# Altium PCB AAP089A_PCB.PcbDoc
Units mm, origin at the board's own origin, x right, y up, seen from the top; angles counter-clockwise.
Board outline 65 x 160 mm, 2 copper layers (Top Layer, Bottom Layer), stack 1.575 mm thick; 87 components, 44 nets, 213 pads, 130 vias.
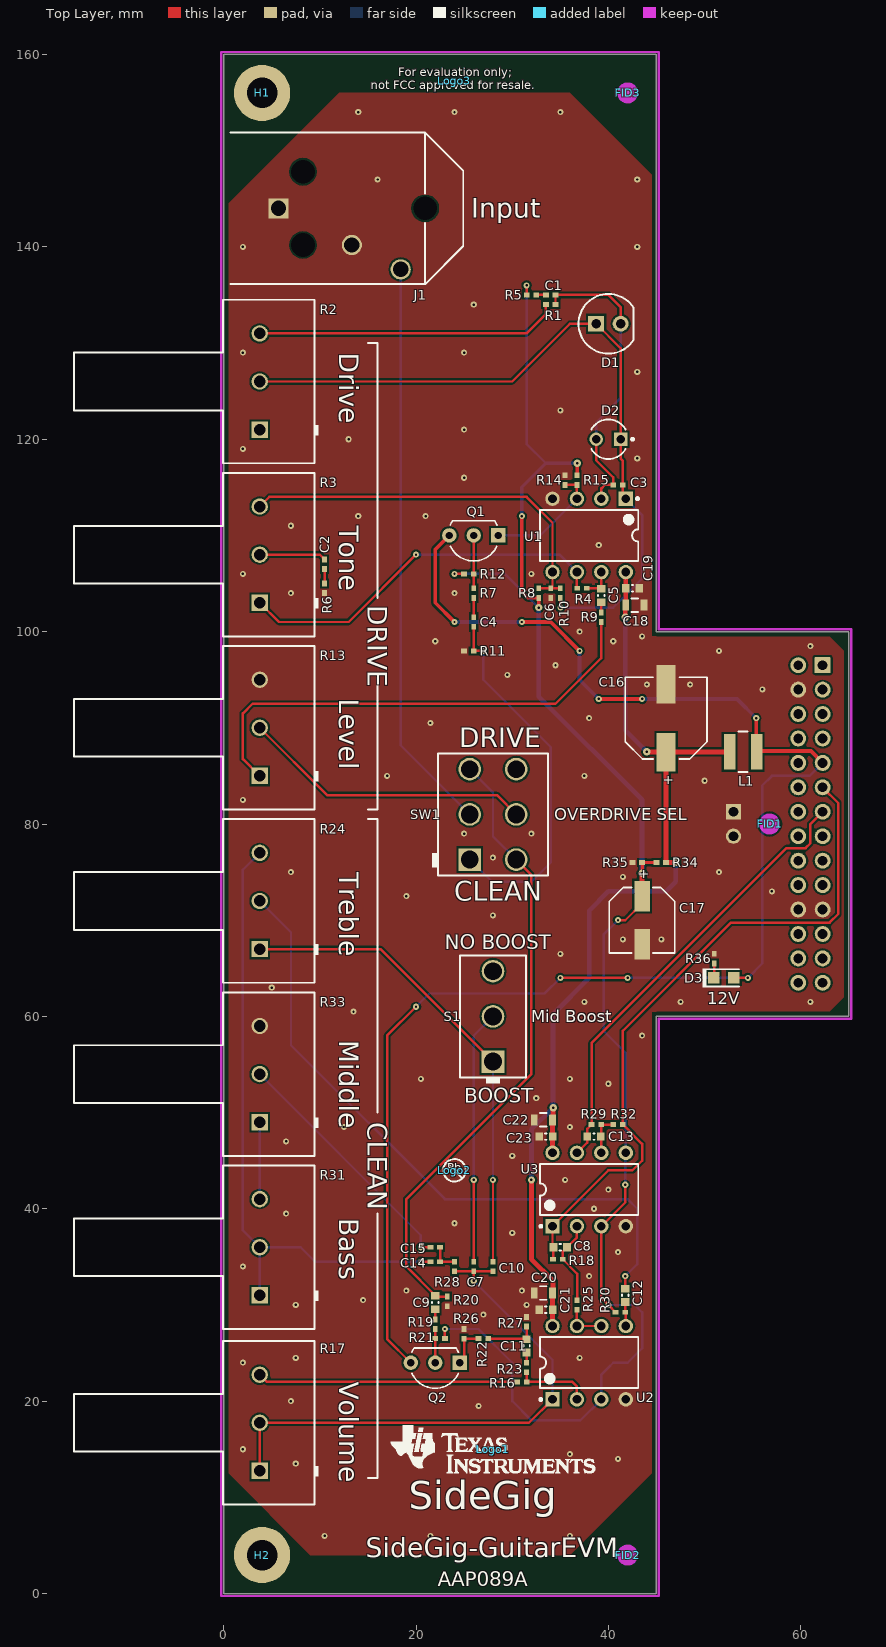
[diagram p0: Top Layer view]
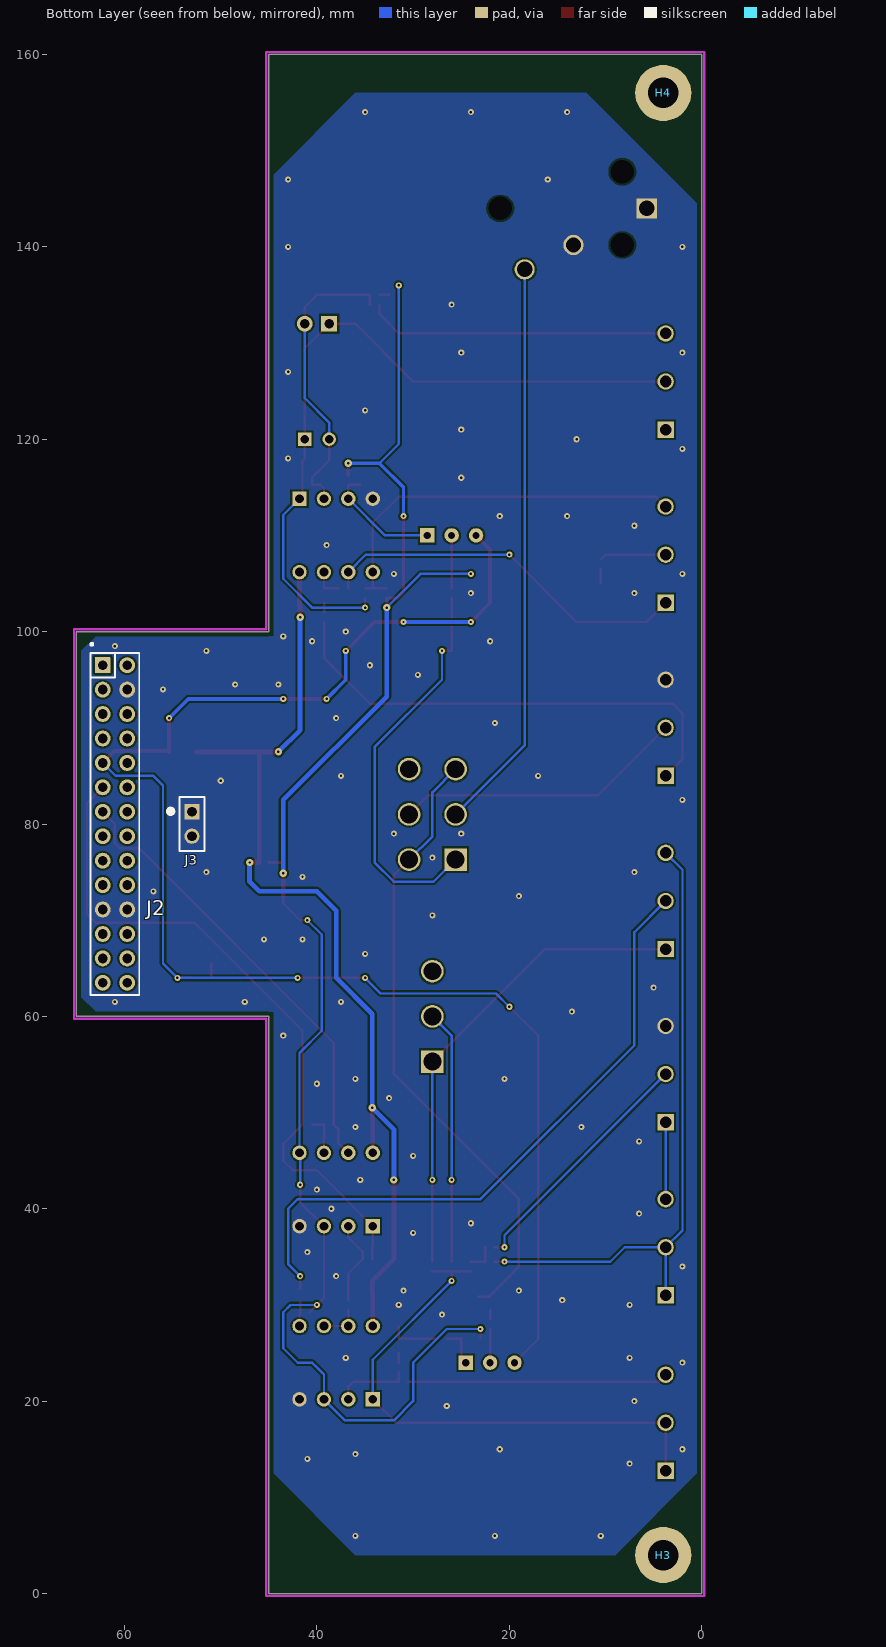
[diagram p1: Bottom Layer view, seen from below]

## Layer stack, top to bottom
Top Solder: solder mask 0.0102, Solder Resist, Dk 3.5
Top Layer: signal copper 0.0356
Dielectric1: core 1.5037, FR-4, Dk 4.8
Bottom Layer: signal copper 0.0356
Bottom Solder: solder mask 0.0102, Solder Resist, Dk 3.5

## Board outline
0,0 45,0 45,60 65,60 65,100 45,100 45,160 0,160

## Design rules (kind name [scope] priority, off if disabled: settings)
AcuteAngle [All] p1: minimum=4.50000000000000E+0001 checktracksonly=FALSE
AssemblyTestPointUsage [All] p1: valid=2
BoardOutlineClearance BoardOutlineClearance_MountingHoles [OnCopper and InComponentClass('Mounting Holes')] p1: gap=0.25
BoardOutlineClearance BoardOutlineClearance_Poly [OnCopper and IsPoly] p2: gap=0.5
BoardOutlineClearance [OnCopper and Not InComponentClass('Logo') and not InComponentClass('FiducialMark') and not InRegion(1000,500,4000,800) and not InPoly] p3: gap=0.5
Clearance Clearance_Keepouts [((IsTrack Or IsArc) And Not InPoly) And IsFree and IsKeepOut vs ((IsTrack Or IsArc) And Not InPoly) And IsFree and IsKeepOut] p1: gap=0
Clearance Clearance_Poly [InPolygon] p2: gap=0.2
Clearance [All] p3: gap=0.2
ComponentClearance ComponentClearance_MountingHoles_FiducialMarks [InComponentClass('Mounting Holes') vs InComponentClass('FiducialMark')] p1: gap=0.25 collisioncheckmode=3 verticalgap=0 showdistances=FALSE
ComponentClearance ComponentClearance_Shunt [InComponentClass('Header') vs InComponentClass('Shunt')] p2: gap=0 collisioncheckmode=3 verticalgap=0 showdistances=FALSE
ComponentClearance ComponentClearance_Logo [InComponentClass('Logo')] p3: gap=1.27 collisioncheckmode=3 verticalgap=0.254 showdistances=FALSE
ComponentClearance ComponentClearance_ScrewToNut [(HasFootprint('NY PMS 440 0025 PH')) vs (HasFootprint('Keystone_1902C'))] p4: gap=0.127 collisioncheckmode=3 verticalgap=0.254 showdistances=FALSE
ComponentClearance ComponentClearance_MountingHoles [InComponentClass('Mounting Holes') vs InComponentClass('Mounting Holes')] p5: gap=0 collisioncheckmode=3 verticalgap=0 showdistances=FALSE
ComponentClearance ComponentClearance_SmallPassives [HasFootprint('0201*') or HasFootprint('0402*') or HasFootprint('0508') or HasFootprint('0603*') or HasFootprint('0612') or HasFootprint('0805*') or HasFootprint('0815*') or HasFootprint('0830*') or HasFootprint('1206*') or HasFootprint('1210*') or HasFootprint('1808*') or HasFootprint('1812*') or HasFootprint('1825*') or HasFootprint('2010*') or HasFootprint('2220*') or HasFootprint('2225*') or HasFootprint('2512*') or HasFootprint('2728*') or HasFootprint('3518*') vs HasFootprint('0201*') or HasFootprint('0402*') or HasFootprint('0508') or HasFootprint('0603*') or HasFootprint('0612') or HasFootprint('0805*') or HasFootprint('0815*') or HasFootprint('0830*') or HasFootprint('1206*') or HasFootprint('1210*') or HasFootprint('1808*') or HasFootprint('1812*') or HasFootprint('1825*') or HasFootprint('2010*') or HasFootprint('2220*') or HasFootprint('2225*') or HasFootprint('2512*') or HasFootprint('2728*') or HasFootprint('3518*')] p6: gap=0.38 collisioncheckmode=3 verticalgap=0.254 showdistances=FALSE
ComponentClearance ComponentClearance_THtoSMT [IsThruComponent vs IsSMTComponent] p7: gap=1.016 collisioncheckmode=3 verticalgap=0.762 showdistances=FALSE
ComponentClearance ComponentClearance_THtoTH [IsThruComponent vs IsThruComponent] p8: gap=0.762 collisioncheckmode=3 verticalgap=0.762 showdistances=FALSE
ComponentClearance [All] p9: gap=0.762 collisioncheckmode=3 verticalgap=0.254 showdistances=FALSE
DiffPairsRouting [All] p1: maxlimit=2.54 minlimit=0.254 mostfreqgap=0.254 toplayer_minwidth=0.381 toplayer_maxwidth=0.381 toplayer_prefwidth=0.381 bottomlayer_minwidth=0.381 bottomlayer_maxwidth=0.381 bottomlayer_prefwidth=0.381 maxuncoupledlength=25.4
FabricationTestPointUsage TestPointUsage [All] p1: valid=2 allowmultiple=FALSE
FabricationTestpoint Testpoint [All] p1: side=3 testpointundercomponent=TRUE minsize=1.016 maxsize=2.54 preferedsize=1.524 minholesize=0 maxholesize=1.016 preferedholesize=0.813 testpointgrid=0.025 allowsidetop=TRUE allowsidebottom=TRUE usegrid=TRUE gridtolerance=0
FanoutControl Fanout_LCC [IsLCC] p1: bgadir=Out bgaviamode=Centered fanoutstyle=Auto fanoutdirection=Alternating viagrid=0.025 // Fanout_LCC (Default Rule)
FanoutControl Fanout_BGA [IsBGA] p2: bgadir=Out bgaviamode=Centered fanoutstyle=Auto fanoutdirection=Alternating viagrid=0.025 // Fanout_BGA (Default Rule)
FanoutControl Fanout_Default [All] p4: bgadir=Out bgaviamode=Centered fanoutstyle=Auto fanoutdirection=Alternating viagrid=0.025 // Fanout_Default (Default Rule)
FanoutControl Fanout_Small [(CompPinCount < 5)] p5: bgadir=Out bgaviamode=Centered fanoutstyle=Auto fanoutdirection=OutThenIn viagrid=0.025 // Fanout_Small (Default Rule)
Height [All] p1: minheight=0 maxheight=38.1 prefheight=12.7
HoleSize [All] p1: absolutevalues=TRUE maxlimit=6.375 minlimit=0.2 maxpercent=80.000 minpercent=20.000
MinimumAnnularRing MinimumAnnularRing_ThermalPadVias [IsVia and InAnyComponent] p1: minimumring=0.15
MinimumAnnularRing [All] p2: minimumring=0.127
MinimumSolderMaskSliver MinimumSolderMaskSliver_Logo [InComponentClass('Logo') vs InComponentClass('Logo')] p1: minsoldermaskwidth=0.018
MinimumSolderMaskSliver [All] p2: minsoldermaskwidth=0.1
PlaneConnect [All] p1: planeconnectstyle=Relief reliefexpansion=0.254 reliefentries=4 reliefconductorwidth=0.254 reliefairgap=0.254
PolygonConnect PreFlood [All] p1: connectstyle=Direct reliefconductorwidth=0.254 reliefentries=4 polygonreliefangle="90 Angle" airgapwidth=0.254
RoutingVias ThermalPadVias [IsVia and InAnyComponent] p1: holewidth=0.2 width=0.5 viastyle="Through Hole" minholewidth=0.2 minwidth=0.5 maxholewidth=0.33 maxwidth=0.6
RoutingVias [All] p2: holewidth=0.254 width=0.635 viastyle="Through Hole" minholewidth=0.254 minwidth=0.635 maxholewidth=1.016 maxwidth=1.651
SilkToBoardRegionClearance [Not ((IsComment or IsDesignator) And (Hide <> 'False')) and not InRegion(1000,500,4000,800)] p1:
SilkToSilkClearance SilkToSilkClearance_Pb-FreeLogo [(HasFootprint('Pb-Free_Overlay_Medium') OR HasFootprint('Pb-Free_Overlay_Small')) vs (HasFootprint('Pb-Free_Overlay_Medium') OR HasFootprint('Pb-Free_Overlay_Small'))] p1: silktosilkclearance=0
SilkToSilkClearance [All] p2: silktosilkclearance=0.102
SilkToSolderMaskClearance SilkToComponentPadClearance [IsPad and InAnycomponent] p1: minsilkscreentomaskgap=0.127 clearancetoexposedcopper=TRUE
SilkToSolderMaskClearance "Silk to Solder Mask Opening" [All] p2: minsilkscreentomaskgap=0.102 clearancetoexposedcopper=FALSE
SolderMaskExpansion [All] p1: expansion=0.05
Width [All] p1: maxlimit=2.54 minlimit=0.152 preferedwidth=0.254 checkconnectedcopper=TRUE
14 further rules are at their usual default settings.

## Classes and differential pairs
component class "Mounting Holes": H1 H2 H3 H4
component class Header: J2
component class AAP089A_SideGig-GuitarEVM: C1 C2 C3 C4 C5 C6 C7 C8 C9 C10 C11 C12 C13 C14 C15 C16 C17 C18 C19 C20 C21 C22 C23 D1 D2 D3 J1 J2 J3 L1 Q1 Q2 R1 R2 R3 R4 R5 R6 R7 R8 R9 R10 R11 R12 R13 R14 R15 R16 R17 R18 R19 R20 R21 R22 R23 R24 R25 R26 R27 R28 R29 R30 R31 R32 R33 R34 R35 R36 S1 SW1 U1 U2 U3
component class Logo: Logo1
component class AAP089A_EVM_Hardware: FID1 FID2 FID3 H1 H2 H3 H4 Logo1 Logo2 Logo3 ZZ1 ZZ2 ZZ3 ZZ4
component class FiducialMark: FID1 FID2 FID3
component class AssemblyNote: ZZ1 ZZ2 ZZ3 ZZ4

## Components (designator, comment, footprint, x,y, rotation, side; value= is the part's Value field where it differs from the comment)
C1 "GRM155R71E473KA88D" 0402L 34,135 r0 top
C2 "GRM155R71C224KA12D" 0402L 10.5,107 r90 top
C3 "GRM1555C1H510JA01D" 0402L 41,115.25 r0 top
C4 "GRM155R71E473KA88D" 0402L 26,101 r90 top
C5 "UMK107AB7105KA-T" 0603L 39.25,103.75 r270 top
C6 "GRM155R71C224KA12D" 0402L 34,104 r90 top
C7 "GRM1555C1H471JA01D" 0402L 26,34 r90 top
C8 "GRM1885C1H220JA01D" 0603L 35,36 r0 top
C9 "C0603C104K5RACTU" 0603L 22,30.25 r270 top
C10 "GRM1555C1H471JA01D" 0402L 28,34 r90 top
C11 "GRM188R61A106ME69D" 0603L 31.5,25.75 r270 top
C12 "GRM188R61A106ME69D" 0603L 41.75,31 r270 top
C13 "GRM1885C1H220JA01D" 0603L 38.5,47.5 r0 top
C14 "GRM155R71H222KA01D" 0402L 22,34.5 r180 top
C15 "GRM155R71H222KA01D" 0402L 22,36 r180 top
C16 "+" SM_RADIAL_F 46,91 r90 top
C17 "+" SM_RADIAL_D 43.5,70 r270 top
C18 "EMK212BJ106KG-T" 0805_KTR 42.75,102.75 r0 top
C19 "C0603C104K5RACTU" 0603L 42.5,104.5 r0 top
C20 "EMK212BJ106KG-T" 0805_KTR 33.25,31.25 r180 top
C21 "C0603C104K5RACTU" 0603L 33.5,29.5 r180 top
C22 "EMK212BJ106KG-T" 0805_KTR 33.25,49.25 r180 top
C23 "C0603C104K5RACTU" 0603L 33.5,47.5 r180 top
D1 "HLMP-3316" HLMP-331_RED 40,132 r0 top
D2 "LTL1CHTBK4" LTL1CH_Blue 40,120 r180 top
D3 "12V" LED_LTST-C171 52,64 r180 top
FID1 "Fiducial" Fiducial10-20 56.75,80 r0 top
FID2 "Fiducial" Fiducial10-20 42,4 r0 top
FID3 "Fiducial" Fiducial10-20 42,156 r0 top
H1 "4-40x1/4\"" B_F_PMSSS4400025PH 4,156 r0 top
H2 "4-40x1/4\"" B_F_PMSSS4400025PH 4,4 r0 top
H3 "4-40x1-1/2\"" Keystone_3483 4,4 r180 bottom
H4 "4-40x1-1/2\"" Keystone_3483 4,156 r180 bottom
J1 "Input" Switchcraft_RN112APC 8.25,144 r180 top
J2 "" TSW-114-07-G-D 61,80 r270 bottom
J3 "PPTC021LFBN-RC" CONN_PPTC021LFBN-RC 53,80 r90 bottom locked
L1 "NRS4012T100MDGJV" NRS4012 54,87.5 r180 top
Logo1 "Texas Instruments" TI_Stacked_Overlay_Small 28,15 r0 top
Logo2 "Pb-Free Symbol" Pb-Free_Overlay_Small 24,44 r0 top
Logo3 "FCC disclaimer" FCC_disclaimer_stacked 24,157.25 r0 top
Q1 "2N4401" TO-92AP 26,110 r180 top
Q2 "2N4401" TO-92AP 22,24 r180 top
R1 "ERJ-2RKF5102X" 0402L 34,134 r180 top
R2 "Drive" BITechnology_P160KN-0QC15 3.75,126 r90 top
R3 "Tone" BITechnology_P160KN-0QC15 3.75,108 r90 top
R4 "CRCW04021K00FKED" 0402L 37.25,104.5 r180 top
R5 "ERJ-2RKF4701X" 0402L 32,135 r180 top
R6 "ERJ-2RKF2200X" 0402L 10.5,104.5 r270 top
R7 "CRCW04021K00FKED" 0402L 26,104 r270 top
R8 "ERJ-2RKF1002X" 0402L 32.75,104 r90 top
R9 "CRCW04021K00FKED" 0402L 39.25,101.5 r90 top
R10 "CRCW04021K00FKED" 0402L 35,104 r270 top
R11 "CRCW04021M50FKED" 0402L 25.5,98 r0 top
R12 "RC0402FR-07470KL" 0402L 25.5,106 r0 top
R13 "Level" BITechnology_P160KN-0QC15 3.75,90 r90 top
R14 "ERJ-2RKF1002X" 0402L 35.5,115.75 r90 top
R15 "ERJ-2RKF1002X" 0402L 36.75,115.75 r90 top
R16 "CRCW04022K74FKED" 0402L 31,22 r0 top
R17 "Volume" BITechnology_P160KN-0QC15 3.75,17.75 r90 top
R18 "ERJ-2RKF1002X" 0402L 34.75,34.75 r180 top
R19 "CRCW04021K00FKED" 0402L 22,28 r90 top
R20 "CRCW04021M50FKED" 0402L 23.25,30.375 r90 top
R21 "RC0402FR-07470KL" 0402L 22.5,26.5 r180 top
R22 "CRCW0402100RFKED" 0402L 27,26.5 r0 top
R23 "CRCW04021K00FKED" 0402L 31.5,23.5 r90 top
R24 "Treble" BITechnology_P160KN-0QC15 3.75,72 r90 top
R25 "ERJ-2RKF1002X" 0402L 36.75,30 r90 top
R26 "ERJ-2RKF1002X" 0402L 25,27 r90 top
R27 "RC0402FR-07470KL" 0402L 31.5,28.25 r270 top
R28 "CRCW040233K2FKED" 0402L 24,34 r90 top
R29 "ERJ-2RKF1002X" 0402L 38.75,48.75 r180 top
R30 "RC0402FR-07470KL" 0402L 41.25,29.25 r0 top
R31 "Bass" BITechnology_P160KN-0QC15 3.75,36 r90 top
R32 "ERJ-2RKF1002X" 0402L 41,48.75 r180 top
R33 "Middle" BITechnology_P160KN-0QC15 3.75,54 r90 top
R34 "ERJ-2RKF1002X" 0402L 45.5,76 r180 top
R35 "ERJ-2RKF1002X" 0402L 43,76 r180 top
R36 "CRCW04021K50FKED" 0402L 51,66 r90 top
S1 "Mid Boost" SW_100SP1T1B1M2QEH 28,60 r90 top
SW1 "OVERDRIVE SEL" SW_100DP1T1B1M2QEH 28,81 r90 top
U1 "RC4558IP" P0008A 38,110 r270 top
U2 "NE5532AP" P0008A 38,24 r90 top
U3 "NE5532AP" P0008A 38,42 r90 top
ZZ1 "U1, U2 and U3 are to be inserted into XU1, XU2, and XU3. Only the dip sockets are to soldered directly to the board." AssemblyNote 4,170 r0 top
ZZ2 "These assemblies are ESD sensitive, ESD precautions shall be observed." AssemblyNote 4,166 r0 top
ZZ3 "These assemblies must be clean and free from flux and all contaminants. Use of no clean flux is not acceptable." AssemblyNote 4,164 r0 top
ZZ4 "These assemblies must comply with workmanship standards IPC-A-610 Class 2, unless otherwise specified." AssemblyNote 4,168 r0 top

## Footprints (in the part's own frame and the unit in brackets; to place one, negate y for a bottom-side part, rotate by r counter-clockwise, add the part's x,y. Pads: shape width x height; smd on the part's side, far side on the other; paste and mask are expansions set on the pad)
0402L [mm] "0402 from SM-752 data"
  rect 0.6x0.5 smd: 1(-0.5,0) 2(0.5,0)
  body extent -0.55,-0.3 0.55,0.3, height 0.6
0603L [mm] "0603 from SM-752 data"
  rect 0.8x0.85 smd: 1(-0.7,0) 2(0.7,0)
  silkscreen extent -0.07,-0.33 0.07,0.33, body extent -0.87,-0.47 0.87,0.47, height 1
0805_KTR [mm] "ROHM"
  rect 0.7x1.15 smd: 1(-0.95,0) 2(0.95,0)
  silkscreen extent -0.35,-0.7 0.35,0.7, body extent -1.05,-0.67 1.05,0.67, height 0.65
AssemblyNote [mm] "Assembly Note"
B_F_PMSSS4400025PH [mil] "MACHINE SCREW PAN PHILLIPS 4-40"
  round 230 hole 125: 1(0,0)
  body extent -109,-109 110,110, height 79
BITechnology_P160KN-0QC15 [mm] "TH, 3-Leads, Body 17x24.5mm"
  rect 1.7x1.7 hole 1.2: 1(-5,0)
  round 1.7 hole 1.2: 2(0,0) 3(5,0)
  silkscreen extent -8.5,-6.1 8.5,19.3, body extent -8.5,-5.7 8.5,19.3, height 21
CONN_PPTC021LFBN-RC [mil] "SULLINS"
  rect 62x62 hole 40: 1(50,0)
  round 62 hole 40.16: 2(-50,0)
  silkscreen extent -111,-51 111,97, body extent -110,-50 110,50, height 336
FCC_disclaimer_stacked [mm]
Fiducial10-20 [mm]
  round 1 smd mask+0.5: 1(0,0)
  Top Layer keep-out circle w1.178: c0,0 r0.5
HLMP-331_RED [mm] "AVAGO"
  rect 1.65x1.65 hole 1: 1(-1.27,0)
  round 1.65 hole 1: 2(1.27,0)
  silkscreen extent -3.1,-3.1 2.6,3.1, body extent -3.05,-3.06 2.57,3.06, height 11.19
Keystone_3483 [mm] "1/4 Round Female Standoff"
  body extent -3.17,-3.17 3.18,3.18, height 38.1
LED_LTST-C171 [mm] "LITE-ON"
  rect 1.2x1.2 smd: 1(-1.05,0) 2(1.05,0)
  silkscreen extent -1.6,-1 2.2,1, body extent -1.05,-0.67 1.05,0.67, height 0.8
LTL1CH_Blue [mm] "TH, 2-Leads, Dia 3.8mm, Pin Spacing 2.54mm"
  rect 1.4x1.4 hole 0.9: 1(-1.27,0)
  round 1.4 hole 0.9: 2(1.27,0)
  silkscreen extent -2.65,-2.05 1.78,2.05, body extent -2.05,-2.05 2.05,2.05, height 6.5
NRS4012 [mm] "2-Leads SMD, Body 4.2x4.2mm, Height 1.2mm"
  rect 1.2x3.7 smd: 1(-1.4,0) 2(1.4,0)
  silkscreen extent -0.49,-2.1 0.49,2.1, body extent -2.1,-2.1 2.1,2.1, height 1.2
P0008A [mm] "DIP, 8-Leads, Row Spacing 7.62mm, Pitch 2.54mm, Body 9.6x6.4mm"
  rect 1.5x1.5 hole 0.9: 1(-3.81,3.81)
  round 1.5 hole 0.9: 2(-3.81,1.27) 3(-3.81,-1.27) 4(-3.81,-3.81) 5(3.81,-3.81) 6(3.81,-1.27) 7(3.81,1.27) 8(3.81,3.81)
  silkscreen extent -3.95,-5.1 2.65,5.15, body extent -4.1,-4.64 4.1,4.64, height 4.22
Pb-Free_Overlay_Small [mm]
  silkscreen extent -1.16,-1.17 1.17,1.17
SM_RADIAL_D [mm] "6.3 x 5.8mm:  Panasonic D"
  rect 3.2x1.6 smd: 1(-2.5,0) 2(2.5,0)
  silkscreen extent -3.4,-3.4 3.4,3.4, body extent -3.4,-3.4 3.4,3.4, height 6.1
SM_RADIAL_F [mm] "8 x 10.2mm:  Panasonic F"
  rect 4x2 smd: 1(-3.55,0) 2(3.55,0)
  silkscreen extent -4.25,-4.25 4.25,4.25, body extent -4.25,-4.25 4.25,4.25, height 10.5
SW_100DP1T1B1M2QEH [mm] "TH, 6-Leads, Body 12.7x11.43mm, Pitch 4.7mm"
  rect 2.35x2.35 hole 1.85: 1(-4.7,2.415)
  round 2.35 hole 1.85: 2(0,2.415) 3(4.7,2.415) 4(-4.7,-2.415) 5(0,-2.415) 6(4.7,-2.415)
  silkscreen extent -6.35,-5.71 6.35,6.36, body extent -6.35,-5.71 6.35,5.72, height 29.99
SW_100SP1T1B1M2QEH [mm] "TH, 3-Leads, Body 12.7x6.86mm, Pitch 4.7mm"
  rect 2.35x2.35 hole 1.85: 1(-4.7,0)
  round 2.35 hole 1.85: 2(0,0) 3(4.7,0)
  silkscreen extent -7,-3.43 6.35,3.43, body extent -6.35,-3.43 6.35,3.43, height 28.49
Switchcraft_RN112APC [mm] "Audio Jack, 3-Pos, R/A, TH"
  rect 2.1x2.1 hole 1.6: 1(2.54,0)
  round 2.1 hole 1.6: 2(-10.16,6.35) 3(-5.08,3.81)
  round 1.524 hole 2.45 unplated: MH1(-12.7,0) MH2(0,3.81) MH3(0,-3.81)
  silkscreen extent -16.66,-7.87 7.54,7.87, body extent -16.66,-7.87 15.85,7.87, height 17.27
TI_Stacked_Overlay_Small [mm]
  silkscreen extent -10.63,-2.49 10.63,2.49
TO-92AP [mm] "TO, Flat Index; 3 In-Line, Axial Leads; Body Dia. 5mm; Leads 0.55 x 0.50 mm (max)"
  rect 1.5x1.5 hole 0.75: 1(-2.54,0)
  round 1.5 hole 0.75: 2(0,0) 3(2.54,0)
  silkscreen extent -2.42,-1.53 2.44,2.66, body extent -2.87,-1.53 2.87,2.66, height 9.33
TSW-114-07-G-D [mm] "Samtec 100mil, 2x14, 230 mil above insulator"
  rrect6% 1.65x1.65 hole 1.016: 1(-16.51,-1.27)
  round 1.65 hole 1.016: 2(-16.51,1.27) 3(-13.97,-1.27) 4(-13.97,1.27) 5(-11.43,-1.27) 6(-11.43,1.27) 7(-8.89,-1.27) 8(-8.89,1.27) 9(-6.35,-1.27) 10(-6.35,1.27) 11(-3.81,-1.27) 12(-3.81,1.27) 13(-1.27,-1.27) 14(-1.27,1.27) 15(1.27,-1.27) 16(1.27,1.27) 17(3.81,-1.27) 18(3.81,1.27) 19(6.35,-1.27) 20(6.35,1.27) 21(8.89,-1.27) 22(8.89,1.27) 23(11.43,-1.27) 24(11.43,1.27) 25(13.97,-1.27) 26(13.97,1.27) 27(16.51,-1.27) 28(16.51,1.27)
  silkscreen extent -18.8,-2.54 17.78,2.54, body extent -17.78,-2.54 17.78,2.54, height 8.38

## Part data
C1 C4: "CAP, CERM, 0.047 µF, 25 V, +/- 10%, X7R, 0402"
C2 C6: "CAP, CERM, 0.22 µF, 16 V, +/- 10%, X7R, 0402"
C3: "CAP, CERM, 51 pF, 50 V, +/- 5%, C0G/NP0, 0402"
C5: "CAP, CERM, 1 µF, 50 V, +/- 10%, X7R, 0603"
C7 C10: "CAP, CERM, 470 pF, 50 V, +/- 5%, C0G/NP0, 0402"
C8 C13: "CAP, CERM, 22 pF, 50 V, +/- 5%, C0G/NP0, 0603"
C9 C19 C21 C23: "CAP, CERM, 0.1 µF, 50 V, +/- 10%, X7R, 0603"
C11 C12: "CAP, CERM, 10 µF, 10 V, +/- 20%, X5R, 0603"
C14 C15: "CAP, CERM, 2200 pF, 50 V, +/- 10%, X7R, 0402"
C16: library part EEE-FC1E101P, "CAP, AL, 100 µF, 25 V, +/- 20%, 0.3 ohm, SMD"
C17: library part EEE-FK1C470P, "CAP, AL, 47 µF, 16 V, +/- 20%, 0.36 ohm, SMD"
C18 C20 C22: "CAP, CERM, 10 µF, 16 V, +/- 10%, X5R, 0805"
D1: "LED, Red, TH"
D2: "LED, Blue, TH"
D3: library part LTST-C171GKT, "LED, Green, SMD"
FID1 FID2 FID3: "Fiducial mark.  There is nothing to buy or mount."
H1 H2: library part "PMSSS 440 0025 PH", "MACHINE SCREW PAN PHILLIPS 4-40"
H3 H4: library part 3483, "1/4 Round Female Standoff, Alum, 1-1/2\""
J1: library part RN112APC, "Audio Jack, 1/4\", Headphone Phone Jack Mono, R/A, Black, TH"
J2: library part TSW-114-07-G-D, "Header, 100mil, 14x2, Gold, TH"
J3: "Receptacle, 100mil, 2x1, Tin, TH"
L1: "Inductor, Wirewound, 10 µH, 0.8 A, 0.204 ohm, SMD"
Logo1: library part TI_Logo, "Texas Instrument Corporate Signature"
Logo2: library part Pb-Free
Logo3: library part FCC_disclaimer, "FCC_disclaimer"
Q1 Q2: library part "2N4401-AP, Micro Commercial Components", "Transistor, NPN, 40 V, 0.5 A, TO-92AP"
R1: "RES, 51.0 k, 1%, 0.1 W, AEC-Q200 Grade 0, 0402"
R2: library part P160KN-0QC15A500K, "Potentiometer 500K 20% 16MM ROTARY POT, TH"
R3 R17 R33: library part P160KN-0QC15B20K, "Potentiometer 20K 20% 16MM ROTARY POT, TH"
R4 R7 R9 R10 R19 R23: "RES, 1.00 k, 1%, 0.063 W, 0402"
R5: "RES, 4.70 k, 1%, 0.1 W, 0402"
R6: "RES, 220, 1%, 0.1 W, AEC-Q200 Grade 0, 0402"
R8 R14 R15 R18 R25 R26 R29 R32 R34 R35: "RES, 10.0 k, 1%, 0.1 W, 0402"
R11 R20: "RES, 1.50 M, 1%, 0.063 W, 0402"
R12 R21 R27 R30: "RES, 470 k, 1%, 0.0625 W, 0402"
R13: library part P160KN-0QC15A100K, "Potentiometer 100K 20% 16MM ROTARY POT, TH"
R16: "RES, 2.74 k, 1%, 0.063 W, 0402"
R22: "RES, 100, 1%, 0.063 W, 0402"
R24: library part P160KN-0QC15B250K, "Potentiometer 250K 20% 16MM ROTARY POT, TH"
R28: "RES, 33.2 k, 1%, 0.063 W, 0402"
R31: library part P160KN-0QC15A1MEG, "Potentiometer 1Meg 20% 16MM ROTARY POT, TH"
R36: "RES, 1.50 k, 1%, 0.063 W, 0402"
S1: library part 100SP1T1B1M2QEH, "Switch, SPDT, On-On, 5 A, 120 VAC, 28 VDC, TH"
SW1: library part 100DP1T1B1M2QEH, "Switch, DPDT, On-On, 5 A, 120 VAC, 28 VDC, TH"
U1: "Dual General-Purpose Operational Amplifier, 10 to 30 V, -40 to 85 degC, 8-pin DIP (P0008A), Pb-Free (RoHS)"
U2 U3: "Dual Low-Noise Operational Amplifier, 10 to 30 V, 0 to 70 degC, 8-pin DIP (P0008A), Pb-Free (RoHS)"
ZZ1 ZZ2 ZZ3 ZZ4: library part AssemblyNote

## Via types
v1: diameter 0.635, hole 0.254, Top Layer to Bottom Layer, tented both sides, 122 vias
v2: diameter 0.762, hole 0.254, Top Layer to Bottom Layer, tented both sides, 8 vias

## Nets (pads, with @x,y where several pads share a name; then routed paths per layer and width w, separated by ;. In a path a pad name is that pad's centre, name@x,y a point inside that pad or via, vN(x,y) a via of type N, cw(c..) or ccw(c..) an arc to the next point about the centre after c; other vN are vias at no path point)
+12V: D3.1 J2.9 L1.1 Q1.3 Q2.3 | length 163
  Top Layer w0.25: Q2.3 17,26.46 17,58 v1(20,61) ; v1(35,64) v1(42,64) ; D3.1 v1(54.5,64)
  Top Layer w0.4: Q1.3 22,108.54 22,103 v1(24,101) ; v1(31,101) 34,101 v1(37,98) ; v1(39,93) v1(43.5,93) ; L1.1@55.375,87.5 55.45,87.575 61.045,87.575 J2.9 ; v1(55.375,91) 55.375,87.525 55.388,87.513 L1.1
  Bottom Layer w0.25: v1(20,61) 21.375,62.375 33.375,62.375 v1(35,64) ; v1(42,64) v1(54.5,64) 56,65.5 56,84 57,85 60.92,85 J2.9
  Bottom Layer w0.4: v1(24,101) v1(31,101) ; v1(37,98) 37,95 v1(39,93) ; v1(43.5,93) 53.375,93 v1(55.375,91)
+12V-OA: C16.1 C18.1 C19.1 C20.1 C21.1 C22.1 C23.1 L1.2 R34.1 U1.8 U2.8 U3.8 | length 104.3
  Top Layer w0.254: C23.1@34.19,47.49 C23.1 ; C22.1 C22.1@34.25,49.3
  Top Layer w0.5: v2(32,43) 32,34.75 34.25,32.5 34.25,31.3 C20.1 C21.1 34.19,29.49 U2.8 ; U3.8 C23.1@34.19,47.49 ; C23.1 C22.1 ; C22.1@34.25,49.3 v2(34.25,50.5) ; v2(41.75,101.5) 41.75,102.7 C18.1 C19.1 41.81,104.51 U1.8 ; v2(44,87.5) L1.2 ; C16.1 R34.1 v2(47,76)
  Bottom Layer w0.5: v2(32,43) 32,48.25 v2(34.25,50.5) 34.25,60.25 38,64 38,71 40,73 46,73 47,74 v2(47,76) ; v2(41.75,101.5) 41.75,89.75 v2(44,87.5)
GND: C6.1 C16.2 C17.2 C18.2 C19.2 C20.2 C21.2 C22.2 C23.2 J1.1 J1.3 J2.4 J2.21 J2.22 J3.1 J3.2 R6.2 R11.1 R13.3 R14.2 R20.1 R26.2 R27.1 R33.3 R35.2 R36.2 U1.4 U2.4 U3.4
  other v1: 10.5,6 21.5,6 36,6 7.5,13.5 41,14 36,14.5 2,15 21,15 26.5,19.5 7,20 2,24 7.5,24.5 37,24.5 27,29 7.5,30 31.5,30 14.5,30.5 19,31.5 31,31.5 38,33 2,34 41,35.5 30,37.5 24,38.5 6.5,39.5 38.5,40 40,42 35.5,43 30,45.5 6.5,47 12.5,48.5 36,48.5 32.5,51.5 40,53 20.5,53.5 36,53.5 43.5,58 13.5,60.5 37.5,61.5 47.5,61.5 61,61.5 5,63 35,66.5 41.5,68 45.5,68 28,70.5 19,72.5 57,73 41.5,74.5 7,75 51.5,75 28,76.5 25,79 32,79 2,82.5 50,84.5 17,85 37.5,85 21.5,90.5 38,91 56,94 44,94.5 48.5,94.5 29.5,95.5 34.5,96.5 51.5,98 61,98.5 22,99 40.5,99 43.5,99.5 37,100 7,104 24,104 2,106 32,106 39,109 7,111 14,112 21,112 25,116 43,118 2,119 13,120 25,121 35,123 43,127 2,129 25,129 26,134 2,140 43,140 16,147 43,147 14,154 24,154 35,154
IN_1: C4.1 R11.2 SW1.1 | length 38.6
  Top Layer w0.25: C4.1 R11.2 v1(27,98)
  Bottom Layer w0.25: SW1.1 27.885,74 32,74 34,76 34,88 27,95 v1(27,98)
IN_2: C9.1 R20.2 SW1.3 SW1.4 | length 65.3
  Top Layer w0.25: C9.1 22.075,30.875 R20.2 ; C9.1@22,31 19,34 19,41 32,54 32,74.715 SW1.4
  Bottom Layer w0.25: SW1.3 28,83.285 28,78.715 SW1.4
NetC1_1: C1.1 R5.1 | length 1
  Top Layer w0.25: R5.1 C1.1
NetC1_2: C1.2 C3.1 D1.2 D2.2 R1.1 U1.2 | length 31
  Top Layer w0.25: R1.1 C1.2 40,135 41.27,133.73 D1.2 ; D2.2 38.73,117.801 40.5,116.031 C3.1 39.625,115.25 39.27,114.895 U1.2
  Bottom Layer w0.25: D2.2 38.73,121.73 41.27,124.27 D1.2
NetC2_1: C2.1 R6.1 | length 1.5
  Top Layer w0.25: R6.1 C2.1
NetC2_2: C2.2 R3.2 | length 7
  Top Layer w0.25: R3.2 10,108 C2.2
NetC3_2: C3.2 D1.1 D2.1 R2.2 R10.2 U1.1 | length 76.7
  Top Layer w0.25: R2.2 30,126 36,132 D1.1 41.27,129.46 D2.1 41.27,117.98 41.5,117.75 C3.2 41.5,114.12 U1.1 ; v1(35,102.5) R10.2
  Bottom Layer w0.25: v1(35,102.5) 40.5,102.5 43.5,105.5 43.5,112.12 U1.1
NetC4_2: C4.2 R7.2 | length 2
  Top Layer w0.25: C4.2 R7.2
NetC5_1: C5.1 R4.1 U1.7 | length 3.2
  Top Layer w0.25: R4.1 39.2,104.5 39.27,104.57 U1.7
NetC5_2: C5.2 R9.2 | length 1
  Top Layer w0.25: R9.2 C5.2@39.25,103
NetC6_2: C6.2 R3.3 R8.2 R10.1 U1.5 | length 41.1
  Top Layer w0.25: R3.3 4.75,114 31.5,114 34.19,111.31 U1.5 34.19,104.69 C6.2 ; R8.2 C6.2 ; R10.1 C6.2
NetC7_1: C7.1 C10.1 R17.1 R17.2 R28.1 U2.1 | length 57.2
  Top Layer w0.25: R17.1 R17.2 31.75,17.75 U2.1 ; R28.1 C7.1 ; v1(26,32.5) C7.1 ; C10.1 C7.1
  Bottom Layer w0.25: v1(26,32.5) 34.19,24.31 U2.1
NetC7_2: C7.2 S1.2 | length 26.3
  Top Layer w0.25: C7.2 v1(26,43)
  Bottom Layer w0.25: v1(26,43) 26,58 S1.2
NetC8_2: C8.2 R18.1 R25.2 U3.2 | length 8.9
  Top Layer w0.25: U3.2 36.73,37.03 C8.2 35.25,35.55 R18.1 36.75,33.25 R25.2
NetC9_2: C9.2 R19.2 | length 1
  Top Layer w0.25: R19.2 C9.2@22,29.5
NetC10_2: C10.2 R24.1 S1.1 | length 49.9
  Top Layer w0.25: R24.1 16.3,67 S1.1 ; C10.2 v1(28,43)
  Bottom Layer w0.25: v1(28,43) S1.1
NetC11_1: C11.1 R22.2 R27.2 | length 5.2
  Top Layer w0.25: R22.2 31.45,26.5 31.5,26.55 R27.2
NetC11_2: C11.2 R23.2 | length 1
  Top Layer w0.25: R23.2 C11.2
NetC12_1: C12.1 R24.2 | length 68.2
  Top Layer w0.25: C12.1 v1(41.75,33)
  Bottom Layer w0.25: R24.2 7,68.75 7,57 23,41 42,41 43,40 43,34.25 v1(41.75,33)
NetC12_2: C12.2 R30.2 U2.5 | length 2.5
  Top Layer w0.25: C12.2 R30.2 41.81,29.19 U2.5
NetC13_2: C13.2 R29.1 R32.2 U3.6 | length 4.2
  Top Layer w0.254: U3.6 39.27,47.43 C13.2 39.25,47.55 R29.1 R32.2
NetC14_1: C14.1 C15.1 R28.2 | length 3
  Top Layer w0.25: C15.1 C14.1 R28.2
NetC14_2: C14.2 R24.3 R31.1 R31.2 | length 65.8
  Top Layer w0.25: v1(20.5,34.5) C14.2
  Bottom Layer w0.25: R31.1 R31.2 ; R24.3 2,75.25 2,37.75 R31.2 ; v1(20.5,34.5) 9.5,34.5 8,36 R31.2
NetC15_2: C15.2 R33.2 | length 25.9
  Top Layer w0.25: v1(20.5,36) C15.2
  Bottom Layer w0.25: R33.2 20.5,37.25 v1(20.5,36)
NetD3_2: D3.2 R36.1 | length 1.5
  Top Layer w0.25: D3.2 51,64.05 R36.1
NetJ1_2: J1.2 SW1.2 | length 59.7
  Bottom Layer w0.25: J1.2 18.41,88.175 SW1.2 ; SW1.2@25.585,80.875 SW1.2@25.625,80.875
NetQ1_1: Q1.1 R14.1 R15.1 U1.3 | length 12.5
  Top Layer w0.25: R14.1 R15.1 36.73,115.23 U1.3
  Bottom Layer w0.25: Q1.1 32.92,110 U1.3
NetQ1_2: Q1.2 R7.1 R12.2 | length 5.5
  Top Layer w0.25: R7.1 R12.2 Q1.2
NetQ2_1: Q2.1 R22.1 R26.1 | length 4.2
  Top Layer w0.25: Q2.1 25,24.46 R26.1 R22.1
NetQ2_2: Q2.2 R19.1 R21.2 | length 3.5
  Top Layer w0.25: Q2.2 R21.2 R19.1
NetR1_2: R1.2 R2.3 | length 31.6
  Top Layer w0.25: R2.3 31.5,131 33.5,133 R1.2
NetR3_1: R3.1 R4.2 U1.6 | length 39.2
  Top Layer w0.25: R3.1 5.75,101 13,101 v1(20,108) ; U1.6 36.73,104.52 R4.2
  Bottom Layer w0.25: v1(20,108) 34.92,108 U1.6
NetR9_1: R9.1 R13.1 | length 50.6
  Top Layer w0.25: R13.1 2,86.75 2,91.5 3,92.5 34.5,92.5 39.25,97.25 R9.1
NetR16_1: R16.1 R17.3 | length 27.1
  Top Layer w0.25: R17.3 4.5,22 R16.1
NetR16_2: R16.2 R23.1 U2.2 | length 7.8
  Top Layer w0.25: R23.1 R16.2 36.25,22 36.73,21.52 U2.2
NetR25_1: R25.1 U2.6 U2.7 | length 4.2
  Top Layer w0.25: R25.1 36.73,29.48 U2.7 U2.6
NetR31_3: R31.3 R33.1 | length 8
  Bottom Layer w0.25: R31.3 R33.1
OUT-A: C8.1 J2.11 R18.2 R32.1 U3.1 | length 71.2
  Top Layer w0.25: R18.2 34.25,35.95 C8.1 34.19,36.11 U3.1 40,44 42.5,44 43.5,45 43.5,46.75 R32.1 41.5,58.5 52.75,69.75 63,69.75 63.9,70.65 63.9,82.18 J2.11
OUT-B: C13.1 J2.13 R29.2 U3.7 | length 47.2
  Top Layer w0.25: U3.7 37.8,46.88 C13.1 37.8,48.3 R29.2 38.25,57.25 58.5,77.5 60.5,77.5 61,78 61,80 J2.13
OUT_1: R13.2 SW1.5 | length 30.4
  Top Layer w0.25: R13.2 10.75,83 28.415,83 SW1.5
VMID: C17.1 R5.2 R8.1 R12.1 R15.2 R21.1 R30.1 R34.2 R35.1 U2.3 U3.3 U3.5 | length 178.5
  Top Layer w0.25: R21.1 v1(23,27.5) ; v1(24,106) R12.1 ; R5.2 v1(31.5,136) ; R30.1 v1(40,30) 39.27,30.73 U3.3 41.75,40.67 v1(41.75,42.5) ; v1(41,70) 41.75,70 43.5,71.75 C17.1
  Top Layer w0.35: v1(31,112) 31,104.125 31.625,103.5 R8.1 v2(32.75,102.5) ; R15.2 v2(36.75,117.5) ; v2(43.5,74.875) R35.1 R34.2
  Top Layer w0.5: C17.1 v2(43.5,74.875)
  Bottom Layer w0.25: v1(23,27.5) 26.5,27.5 30,24 30,20 32,18 37.08,18 U2.3 39.27,22.77 40,23.5 40.5,24 42,24 43.5,25.5 43.5,29.25 42.75,30 v1(40,30) ; v1(24,106) 29.25,106 v2(32.75,102.5) ; v1(31.5,136) 31.5,119.5 33.5,117.5 ; v1(41,70) 39.5,68.5 39.5,58.5 41.81,56.19 U3.5 41.75,45.75 v1(41.75,42.5)
  Bottom Layer w0.35: v1(31,112) 31,115 33.5,117.5 v2(36.75,117.5)
  Bottom Layer w0.5: v2(32.75,102.5) 32.75,93.25 43.5,82.5 v2(43.5,74.875)
pads on no net: FID1.1 FID2.1 FID3.1 H1.1 H2.1 J1.MH1 J1.MH2 J1.MH3 J2.1 J2.2 J2.3 J2.5 J2.6 J2.7 J2.8 J2.10 J2.12 J2.14 J2.15 J2.16 J2.17 J2.18 J2.19 J2.20 J2.23 J2.24 J2.25 J2.26 J2.27 J2.28 R2.1 S1.3 SW1.6

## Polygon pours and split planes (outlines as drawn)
GND on Top Layer "GND Top Copper" (solid, remove dead copper, pour order 0): 0.5,144.5 12,156 36,156 44.5,147.5 44.5,99.5 63,99.5 64.5,98 64.5,62 63,60.5 44.5,60.5 44.5,12.5 36,4 9,4 0.5,12.5
GND on Bottom Layer "GND Bottom Copper" (solid, remove dead copper, pour order 2): 0.5,144.5 12,156 36,156 44.5,147.5 44.5,99.5 63,99.5 64.5,98 64.5,62 63,60.5 44.5,60.5 44.5,12.5 36,4 9,4 0.5,12.5

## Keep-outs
Keep-Out Layer:
  lines w0.25: -0.25,-0.25 -0.25,160.25 45.25,160.25 45.25,100.25 65.25,100.25 65.25,59.75 45.25,59.75 45.25,-0.25 -0.25,-0.25

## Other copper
Top Layer:
  text ".Layer_Name" at 4.656,-21.806 h1.52
Bottom Layer:
  text ".Layer_Name" at 4.656,-21.806 h1.52

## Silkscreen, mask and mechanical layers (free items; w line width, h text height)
Top Overlay:
  lines w0.2: 15,12 16,12 16,39.5 ; 15,80.5 16,80.5 16,50 ; 15,81.5 16,81.5 16,95.25 ; 15,130 16,130 16,103.5
  text "DRIVE" at 15,102.75 h2 r270
  text "DRIVE" at 24.5,88 h2
  text "CLEAN" at 24,72 h2
  text "NO BOOST" at 23,67 h1.5
  text "BOOST" at 25,51 h1.5
  text "CLEAN" at 15,49 h2 r270
  text "SideGig" at 19.25,7.75 h5
  text "SideGig-GuitarEVM" at 14.75,3.75 h2
  text "AAP089A" at 22.25,0.75 h1.5
  text ".Layer_Name" at 4.656,-21.806 h1.52
Bottom Overlay:
  text ".Layer_Name" at 4.656,-21.806 h1.52
Top Paste:
  text ".Layer_Name" at 4.656,-21.806 h1.52
Bottom Paste:
  text ".Layer_Name" at 4.656,-21.806 h1.52
Top Solder:
  text ".Layer_Name" at 4.656,-21.806 h1.52
Bottom Solder:
  text ".Layer_Name" at 4.656,-21.806 h1.52
Drill Guide:
  text ".Layer_Name" at 76,42 h1.52
M1 Board Outline:
  the board outline again, w0.254
  text ".Layer_Name" at 46.5,-22 h1.52
M2 Board Dimensions:
  text ".Layer_Name" at 72.5,-22 h1.52
M3 3D STEP Top:
  text ".Layer_Name" at 4.656,-21.806 h1.52
M4 3D STEP Bottom:
  text ".Layer_Name" at 4.656,-21.806 h1.52
M5 Assembly Top:
  lines w0.254: -17.417,-23.626 150.223,-23.626 ; -17.417,-18.462 150.274,-18.462 ; -17.417,-13.297 -17.417,-28.791 84.31,-28.791 150.274,-28.791 150.274,-13.297 -17.404,-13.297 -17.404,-28.791 22.614,-28.791 ; 45.194,-28.791 45.194,-13.297 ; 77.376,-18.462 77.376,-13.297 ; 98.712,-18.462 98.712,-13.297 ; 114.511,-28.956 114.511,-23.804
  text "PCB VIEWED FROM TOP SIDE" at -15.804,-16.654 h1.52
  text "BOARD #:" at 47.099,-16.654 h1.52
  text ".PRJ_Number" at 60.955,-16.654 h1.52
  text "REV:" at 82.405,-16.654 h1.52
  text ".PCB_Rev" at 89.809,-16.654 h1.52
  text "SVN REV:" at 103.69,-16.654 h1.52
  text ".VersionControl_RevNumber" at 116.543,-16.654 h1.52
  text "PLOT NAME =" at -15.804,-27.034 h1.52
  text ".plot_File_Name" at 4.656,-27.034 h1.52
  text "GENERATED    :" at 47.15,-27.034 h1.52
  text ".Print_Date" at 69.235,-27.034 h1.52
  text ".Print_Time" at 87.752,-27.034 h1.52
  text "TEXAS INSTRUMENTS" at 119.87,-27.034 h1.52
M6 Assembly Bottom:
  lines w0.254: -17.43,-18.474 150.261,-18.474 ; -17.379,-23.639 150.261,-23.639 ; 18.334,-28.969 18.334,-23.817 ; 34.132,-18.474 34.132,-13.31 ; 55.468,-18.474 55.468,-13.31 ; 87.65,-28.804 87.65,-13.31 ; 110.231,-28.804 150.249,-28.804 150.249,-13.31 -17.43,-13.31 -17.43,-28.804 48.534,-28.804 150.261,-28.804 150.261,-13.31
  text ".VersionControl_RevNumber" at 16.302,-16.667 h1.52
  text "SVN REV:" at 29.154,-16.667 h1.52
  text ".PCB_Rev" at 43.035,-16.667 h1.52
  text "REV:" at 50.439,-16.667 h1.52
  text ".PRJ_Number" at 71.89,-16.667 h1.52
  text "BOARD #:" at 85.745,-16.667 h1.52
  text "PCB VIEWED FROM BOTTOM SIDE" at 148.648,-16.667 h1.52
  text "TEXAS INSTRUMENTS" at 12.974,-27.047 h1.52
  text ".Print_Time" at 45.093,-27.047 h1.52
  text ".Print_Date" at 63.609,-27.047 h1.52
  text "GENERATED    :" at 85.694,-27.047 h1.52
  text ".plot_File_Name" at 128.189,-27.047 h1.52
  text "PLOT NAME =" at 148.648,-27.047 h1.52
M9 Title Sheet:
  drawing of 57 lines, arcs and shapes, not listed
  text "1" at 8.792,204.127 h1.78
  text "2" at 72.182,204.127 h1.78
  text "3" at 135.411,204.127 h1.78
  text "4" at 199.08,204.127 h1.78
  text "5" at 262.555,204.127 h1.78
  text "6" at 326.182,204.127 h1.78
  text "A" at -20.579,175.095 h1.78
  text "A" at 355.341,175.095 h1.78
  text "B" at -20.579,114.643 h1.78
  text "B" at 355.341,114.643 h1.78
  text "C" at -20.579,54.318 h1.78
  text "C" at 355.341,54.318 h1.78
  text "PROJECT TITLE:" at 278.125,7.048 h1.14
  text ".PRJ_Title" at 279.395,3.662 h1.78
  text "DESIGNED FOR:" at 278.125,-0.597 h1.14
  text ".PRJ_Customer" at 279.395,-4.153 h1.78
  text "D" at -20.579,-5.88 h1.78
  text "D" at 355.341,-5.88 h1.78
  text "FILE NAME:" at 278.125,-8.217 h1.14
  text ".PCB_File_Name_No_Path" at 279.395,-11.265 h1.78
  text "Texas Instruments (TI) and/or its licensors do not warrant the accuracy or completeness of this specification" at 151.9,-15.376 h1.14
  text "ENGINEER:" at 278.125,-15.583 h1.14
  text "LAYOUT BY:" at 316.352,-15.583 h1.14
  text "or any information contained therein. TI and/or its licensors do not warrant that this design will meet" at 150.757,-18.237 h1.14
  text ".PRJ_Engineer" at 279.395,-19.52 h1.78
  text ".PCB_Layout" at 317.635,-19.52 h1.78
  text "the specifications, will be suitable for your application or fit for any particular purpose, or will operate in" at 150.757,-21.099 h1.14
  text "ALTIUM DESIGNER VERSION:" at 316.352,-23.457 h1.14
  text "an implementation. TI and/or its licensors do not warrant that the design is production worthy. You should" at 150.757,-23.961 h1.14
  text "completely validate and test your design implementation to confirm the system functionality for your application." at 151.9,-26.822 h1.14
  text ".print_Scale" at 279.395,-26.843 h1.78
  text ".Application_BuildNumber" at 317.635,-26.843 h1.78
  text "1" at 8.792,-32.093 h1.78
  text "2" at 72.182,-32.093 h1.78
  text "3" at 135.411,-32.093 h1.78
  text "4" at 199.08,-32.093 h1.78
  text "5" at 262.555,-32.093 h1.78
  text "6" at 326.182,-32.093 h1.78
M10 Fab Notes:
  drawing of 173 lines, arcs and shapes, not listed
  text ".Layer_Name" at 276.75,161 h1.52
  text "DESIGN INFORMATION" at 304.402,157.505 h1.52
  text "MIN. TRACK WIDTH:" at 288.03,152.933 h1.52
  text "8" at 315.874,152.933 h1.52
  text "MIL" at 319.805,152.933 h1.52
  text "MIN. CLEARANCE:" at 288.03,149.581 h1.52
  text "0.2" at 314.35,149.581 h1.52
  text "mm" at 319.805,149.581 h1.52
  text "MIN. VIA PAD SIZE:" at 288.03,146.228 h1.52
  text "20" at 315.113,146.228 h1.52
  text "MIL" at 319.805,146.228 h1.52
  text "0.05mm (2MIL)" at 305.683,142.628 h1.52
  text "MINIMUM ANNULAR RING" at 279.667,142.52 h1.52
  text "EXTERNAL" at 323.666,142.52 h1.52
  text "PER" at 284.747,139.522 h1.52
  text "IPC-D-275 CLASS 2 LEVEL C" at 290.335,139.522 h1.52
  text "MIL, HOLES" at 328.136,136.67 h1.52
  text "+/-" at 318.168,136.652 h1.52
  text "+/-" at 339.86,136.652 h1.52
  text "REGISTRATION TOLERANCES:" at 279.667,136.525 h1.52
  text "METAL" at 310.142,136.525 h1.52
  text "5" at 324.777,136.525 h1.52
  text "3" at 345.935,136.525 h1.52
  text "MIL" at 348.888,136.525 h1.52
  text "+/-" at 339.86,133.655 h1.52
  text "HOLE SIZE TOLERANCE (UNLESS OTHERWISE SPECIFIED):" at 279.667,133.528 h1.52
  text "3" at 345.935,133.528 h1.52
  text "MIL" at 348.888,133.528 h1.52
  text "MATERIAL:" at 277.768,128.208 h1.52
  text "FR-4 High Tg" at 302.824,124.643 h1.52
  text "FR-408" at 288.462,124.425 h1.52
  text "OTHER" at 326.257,124.425 h1.52
  text "X" at 298.889,124.333 h1.52
  text "62 MIL (1.6mm) +/-10%" at 296.592,120.292 h1.52
  text "THICKNESS:" at 279.667,120.184 h1.52
  text "X" at 293.337,120.184 h1.52
  text "OTHER" at 329.229,120.184 h1.52
  text "TOLERANCE:" at 279.667,116.17 h1.52
  text "X" at 300.986,116.17 h1.52
  text "ANSI IPC-6012 TYPE 3 CLASS 2" at 305.734,116.17 h1.52
  text "OTHER +/-" at 305.734,112.208 h1.52
  text "BOW & TWIST:" at 279.667,108.22 h1.52
  text "X" at 300.986,108.22 h1.52
  text "ANSI IPC-6012 TYPE 3 CLASS 2" at 305.734,108.22 h1.52
  text "OTHER +/-" at 305.734,104.194 h1.52
  text "DRILLING:" at 277.768,100.676 h1.52
  text "REFERENCE:" at 279.667,97.705 h1.52
  text "X" at 296.132,97.705 h1.52
  text "AS SHOWN" at 300.882,97.705 h1.52
  text "X" at 319.018,97.705 h1.52
  text "NC_DRILL FILES" at 322.498,97.705 h1.52
  text "PTH COPPER THICKNESS:" at 279.667,93.691 h1.52
  text "X" at 308.375,93.691 h1.52
  text "20-30 um" at 311.855,93.691 h1.52
  text "OTHER" at 330.067,93.691 h1.52
  text "BOARD FINISH:" at 277.768,89.653 h1.52
  text "SILKSCREEN:" at 281.711,86.656 h1.52
  text "X" at 305.81,86.656 h1.52
  text "TOP" at 309.01,86.656 h1.52
  text "X" at 318.764,86.656 h1.52
  text "BOTTOM" at 321.99,86.656 h1.52
  text "SILKSCREEN COLOR:" at 281.711,82.414 h1.52
  text "X" at 305.783,82.414 h1.52
  text "WHITE" at 309.01,82.414 h1.52
  text "OTHER" at 321.99,82.414 h1.52
  text "X" at 309.111,78.37 h1.52
  text "BLUE" at 312.338,78.37 h1.52
  text "OTHER" at 328.035,78.37 h1.52
  text "SOLDER RESIST COLOR:" at 281.711,78.096 h1.52
  text "X" at 309.111,74.052 h1.52
  text "MATTE" at 312.338,74.052 h1.52
  text "SEMI-GLOSS" at 328.023,74.036 h1.52
  text "IMMERSION GOLD (ENIG)" at 304.718,69.264 h1.52
  text "ENEPIG" at 338.691,69.18 h1.52
  text "SURFACE FINISH:" at 277.768,69.155 h1.52
  text "X" at 299.969,69.155 h1.52
  text "IMM. TIN/SILVER OR EQUIV" at 286.139,65.167 h1.52
  text "OTHER" at 322.498,65.167 h1.52
  text "ARRAY/PANEL:" at 277.768,60.621 h1.52
  text "CUT AND TRIM PER M1 BOARD OUTLINE" at 304.718,60.512 h1.52
  text "N.C. ROUTE" at 304.718,56.658 h1.52
  text "X" at 321.964,56.658 h1.52
  text "V. SCORE" at 326.714,56.658 h1.52
  text "CERTIFICATION:" at 277.768,53.178 h1.52
  text "MATERIALS AND WORKMANSHIP FOR ALL PCBS" at 296.183,53.178 h1.52
  text "TO MEET OR EXCEED THE REQUIREMENTS OF:" at 296.183,50.689 h1.52
  text "X" at 286.696,47.222 h1.52
  text "ANSI IPC-A-600F CLASS ->" at 290.227,47.222 h1.52
  text "X" at 331.859,47.222 h1.52
  text "2" at 334.88,47.222 h1.52
  text "1" at 326.879,47.184 h1.52
  text "3" at 343.872,47.184 h1.52
  text "X" at 307.373,43.171 h1.52
  text "RoHS" at 310.852,43.171 h1.52
  text "OTHER" at 327.22,43.171 h1.52
  text "PER ORDER" at 337.305,43.171 h1.52
  text "ALL BOARDS MUST MEET OR EXCEED UL94-V0 REQUIREMENTS." at 278.468,38.964 h1.52
  text "PCB MUST BEAR THE UL94V-0 UL REGISTERED MATERIAL ID NUMBER" at 278.468,35.916 h1.52
  text "ADDITIONAL REQUIREMENTS:" at 277.768,31.512 h1.52
  text "MICROSECTION:" at 279.667,28.591 h1.52
  text "YES" at 302.673,28.591 h1.52
  text "REQUIRED" at 324.555,24.625 h1.52
  text "BARE BOARD ELEC. TEST:" at 279.667,24.553 h1.52
  text "NONE" at 312.833,24.553 h1.52
  text "X" at 321.329,24.553 h1.52
  text "PER ORDER" at 339.592,24.553 h1.52
M11 Gerber Information:
  lines w0.254: -17.417,-23.626 150.223,-23.626 ; -17.417,-18.462 150.274,-18.462 ; -17.417,-13.297 -17.417,-28.791 84.31,-28.791 150.274,-28.791 150.274,-13.297 -17.404,-13.297 -17.404,-28.791 22.614,-28.791 ; 45.194,-28.791 45.194,-13.297 ; 77.376,-18.462 77.376,-13.297 ; 98.712,-18.462 98.712,-13.297 ; 114.511,-28.956 114.511,-23.804
  text "ALL ARTWORK VIEWED FROM TOP SIDE" at -15.804,-16.654 h1.52
  text "BOARD #:" at 47.099,-16.654 h1.52
  text ".PRJ_Number" at 60.955,-16.654 h1.52
  text "REV:" at 82.405,-16.654 h1.52
  text ".PCB_Rev" at 89.809,-16.654 h1.52
  text "SVN REV:" at 103.69,-16.654 h1.52
  text ".VersionControl_RevNumber" at 116.543,-16.654 h1.52
  text "LAYER NAME =" at -15.804,-21.806 h1.52
  text "PLOT NAME =" at -15.804,-27.034 h1.52
  text ".plot_File_Name" at 4.656,-27.034 h1.52
  text "GENERATED    :" at 47.15,-27.034 h1.52
  text ".Print_Date" at 69.235,-27.034 h1.52
  text ".Print_Time" at 87.752,-27.034 h1.52
  text "TEXAS INSTRUMENTS" at 119.87,-27.034 h1.52
M12 Stackup:
  drawing of 191 lines, arcs and shapes, not listed
  text ".Layer_Name" at 76,74 h1.52
  text "Layer" at 76.714,70.289 h1.52
  text "Name" at 87.126,70.289 h1.52
  text "Material" at 110.742,70.289 h1.52
  text "Thickness" at 132.58,70.289 h1.52
  text "Constant" at 149.086,70.289 h1.52
  text "Board Layer Stack" at 163.56,70.289 h1.52
  text "1" at 76.714,67.241 h1.52
  text "Top Overlay" at 87.126,67.241 h1.52
  text "2" at 76.714,64.193 h1.52
  text "Top Solder" at 87.126,64.193 h1.52
  text "Solder Resist" at 110.742,64.193 h1.52
  text "0.40mil" at 132.58,64.193 h1.52
  text "3.5" at 149.086,64.193 h1.52
  text "3" at 76.714,61.145 h1.52
  text "Top Layer" at 87.126,61.145 h1.52
  text "Copper" at 110.742,61.145 h1.52
  text "1.40mil" at 132.58,61.145 h1.52
  text "4" at 76.714,58.097 h1.52
  text "Dielectric1" at 87.126,58.097 h1.52
  text "FR-4" at 110.742,58.097 h1.52
  text "59.20mil" at 132.58,58.097 h1.52
  text "4.8" at 149.086,58.097 h1.52
  text "5" at 76.714,55.049 h1.52
  text "Bottom Layer" at 87.126,55.049 h1.52
  text "Copper" at 110.742,55.049 h1.52
  text "1.40mil" at 132.58,55.049 h1.52
  text "6" at 76.714,52.001 h1.52
  text "Bottom Solder" at 87.126,52.001 h1.52
  text "Solder Resist" at 110.742,52.001 h1.52
  text "0.40mil" at 132.58,52.001 h1.52
  text "3.5" at 149.086,52.001 h1.52
  text "7" at 76.714,48.953 h1.52
  text "Bottom Overlay" at 87.126,48.953 h1.52
M13 Component Bodies Top:
  text ".Layer_Name" at 4.656,-21.806 h1.52
M14 Component Bodies Bottom:
  text ".Layer_Name" at 4.656,-21.806 h1.52
M15 Courtyards Top:
  text ".Layer_Name" at 4.656,-21.806 h1.52
M16 Courtyards Bottom:
  text ".Layer_Name" at 4.656,-21.806 h1.52
Drill Drawing:
  circle w0.254: c77.129,17.615 r0.422
  circle w0.254: c77.129,17.615 r0.703
  lines w0.254: 76.426,4.615 76.778,4.615 76.778,4.263 77.481,4.263 77.481,4.615 77.832,4.615 77.832,5.317 77.481,5.317 77.481,5.669 76.778,5.669 76.778,5.317 76.426,5.317 76.426,4.615 ; 76.426,7.426 77.832,7.426 77.832,8.831 76.426,8.831 76.426,7.426 ; 76.426,10.939 76.778,10.939 77.129,10.588 77.481,10.939 77.832,10.939 77.481,11.291 77.832,11.642 77.481,11.642 77.129,11.993 76.778,11.642 76.426,11.642 76.778,11.291 76.426,10.939 ; 76.426,14.102 76.778,14.102 76.778,13.75 77.481,13.75 77.481,14.102 77.832,14.102 77.832,14.804 77.481,14.804 77.481,15.156 76.778,15.156 76.778,14.804 76.426,14.804 76.426,14.102 ; 76.426,20.075 77.832,20.075 77.832,21.48 76.426,21.48 76.426,20.075 ; 76.426,23.237 76.426,23.589 76.778,23.94 76.426,24.291 76.426,24.643 76.778,24.643 77.129,24.291 77.481,24.643 77.832,24.643 77.832,24.291 77.481,23.94 77.832,23.589 77.832,23.237 77.481,23.237 77.129,23.589 76.778,23.237 76.426,23.237 ; 76.426,26.399 77.129,26.751 77.832,26.399 77.481,27.102 77.832,27.805 77.129,27.454 76.426,27.805 76.778,27.102 76.426,26.399 ; 76.426,30.265 77.129,29.562 77.832,30.265 77.129,30.967 76.426,30.265 ; 76.426,32.724 77.129,33.075 77.832,32.724 77.481,33.427 77.832,34.13 77.129,33.778 76.426,34.13 76.778,33.427 76.426,32.724 ; 76.426,36.238 76.778,36.238 77.129,35.886 77.481,36.238 77.832,36.238 77.481,36.589 77.832,36.94 77.481,36.94 77.129,37.292 76.778,36.94 76.426,36.94 76.778,36.589 76.426,36.238 ; 76.708,4.755 76.918,4.755 76.918,4.544 77.34,4.544 77.34,4.755 77.551,4.755 77.551,5.177 77.34,5.177 77.34,5.388 76.918,5.388 76.918,5.177 76.708,5.177 76.708,4.755 ; 76.708,11.08 76.918,11.08 77.129,10.869 77.34,11.08 77.551,11.08 77.34,11.291 77.551,11.502 77.34,11.502 77.129,11.712 76.918,11.502 76.708,11.502 76.918,11.291 76.708,11.08 ; 76.708,20.356 77.551,20.356 77.551,21.199 76.708,21.199 76.708,20.356 ; 76.708,33.005 77.129,33.216 77.551,33.005 77.34,33.427 77.551,33.848 77.129,33.638 76.708,33.848 76.918,33.427 76.708,33.005
  lines w0.305: 75.152,3.315 157.25,3.315 ; 75.152,38.1 157.25,38.1 ; 83.738,0.152 83.738,41.262 ; 92.175,0.152 92.175,41.262 ; 108.341,0.152 108.341,41.262 ; 114.925,0.152 114.925,41.262 ; 124.456,0.152 124.456,41.262 ; 142.86,0.152 142.86,41.262 ; 75.152,0.152 157.25,0.152 157.25,41.262 75.152,41.262 75.152,0.152
  text "Symbol" at 77.05,39.049 h1.83
  text "Quantity" at 84.687,39.049 h1.83
  text "Finished Hole Size" at 93.123,39.049 h1.83
  text "Plated" at 109.29,39.049 h1.83
  text "Hole Type" at 115.874,39.049 h1.83
  text "Drill Layer Pair" at 125.405,39.049 h1.83
  text "Hole Tolerance" at 143.808,39.049 h1.83
  text "3" at 84.687,35.886 h1.52
  text "2.450mm (96.46mil)" at 93.123,35.886 h1.52
  text "NPTH" at 109.29,35.886 h1.52
  text "Round" at 115.874,35.886 h1.52
  text "Top Layer - Bottom Layer" at 125.405,35.886 h1.52
  text "130" at 84.687,32.724 h1.52
  text "0.254mm (10.00mil)" at 93.123,32.724 h1.52
  text "PTH" at 109.29,32.724 h1.52
  text "Round" at 115.874,32.724 h1.52
  text "Top Layer - Bottom Layer" at 125.405,32.724 h1.52
  text "6" at 84.687,29.562 h1.52
  text "0.750mm (29.53mil)" at 93.123,29.562 h1.52
  text "PTH" at 109.29,29.562 h1.52
  text "Round" at 115.874,29.562 h1.52
  text "Top Layer - Bottom Layer" at 125.405,29.562 h1.52
  text "26" at 84.687,26.399 h1.52
  text "0.900mm (35.43mil)" at 93.123,26.399 h1.52
  text "PTH" at 109.29,26.399 h1.52
  text "Round" at 115.874,26.399 h1.52
  text "Top Layer - Bottom Layer" at 125.405,26.399 h1.52
  text "2" at 84.687,23.237 h1.52
  text "1.000mm (39.37mil)" at 93.123,23.237 h1.52
  text "PTH" at 109.29,23.237 h1.52
  text "Round" at 115.874,23.237 h1.52
  text "Top Layer - Bottom Layer" at 125.405,23.237 h1.52
  text "29" at 84.687,20.075 h1.52
  text "1.016mm (40.00mil)" at 93.123,20.075 h1.52
  text "PTH" at 109.29,20.075 h1.52
  text "Round" at 115.874,20.075 h1.52
  text "Top Layer - Bottom Layer" at 125.405,20.075 h1.52
  text "1" at 84.687,16.913 h1.52
  text "1.020mm (40.16mil)" at 93.123,16.913 h1.52
  text "PTH" at 109.29,16.913 h1.52
  text "Round" at 115.874,16.913 h1.52
  text "Top Layer - Bottom Layer" at 125.405,16.913 h1.52
  text "21" at 84.687,13.75 h1.52
  text "1.200mm (47.24mil)" at 93.123,13.75 h1.52
  text "PTH" at 109.29,13.75 h1.52
  text "Round" at 115.874,13.75 h1.52
  text "Top Layer - Bottom Layer" at 125.405,13.75 h1.52
  text "+0.200mm" at 143.808,13.75 h1.52
  text "3" at 84.687,10.588 h1.52
  text "1.600mm (62.99mil)" at 93.123,10.588 h1.52
  text "PTH" at 109.29,10.588 h1.52
  text "Round" at 115.874,10.588 h1.52
  text "Top Layer - Bottom Layer" at 125.405,10.588 h1.52
  text "9" at 84.687,7.426 h1.52
  text "1.850mm (72.83mil)" at 93.123,7.426 h1.52
  text "PTH" at 109.29,7.426 h1.52
  text "Round" at 115.874,7.426 h1.52
  text "Top Layer - Bottom Layer" at 125.405,7.426 h1.52
  text "2" at 84.687,4.263 h1.52
  text "3.175mm (125.00mil)" at 93.123,4.263 h1.52
  text "PTH" at 109.29,4.263 h1.52
  text "Round" at 115.874,4.263 h1.52
  text "Top Layer - Bottom Layer" at 125.405,4.263 h1.52
  text "232 Total" at 84.687,1.101 h1.52
  text ".Layer_Name" at 4.656,-21.806 h1.52
Hole Dims:
  circle w0.254: c4,4 r1.625
  circle w0.254: c4,156 r1.625

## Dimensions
-15.55,14 to 0,-0.5 on M16 Courtyards Bottom
-0.5,0 to -0.5,160 on M2 Board Dimensions
0,-0.5 to 45,-0.5 on M2 Board Dimensions
45,160.5 to 65,100.5 on M2 Board Dimensions
45,100 to 45.5,160 on M2 Board Dimensions
45.5,0 to 65.5,60 on M2 Board Dimensions
0,-0.5 to 4,-0.5 on M16 Courtyards Bottom
-0.5,4 to -0.5,0 on M16 Courtyards Bottom
-0.5,156 to -0.5,0 on M16 Courtyards Bottom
